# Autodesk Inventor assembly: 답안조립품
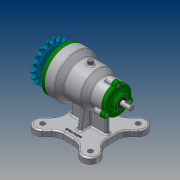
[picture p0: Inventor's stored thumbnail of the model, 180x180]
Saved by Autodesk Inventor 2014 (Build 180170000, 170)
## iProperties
Created: 2017-03
Part Number: 답안조립품
Document SubType Name: Assembly
Designer: Administrator
Author: Administrator
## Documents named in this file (14)
- C:\Users\Administrator\Desktop\470308V1007\답안조립품.iam
- C:\Users\Administrator\Desktop\470308V1007\본체.ipt
- C:\Users\Administrator\Desktop\470308V1007\뒤커버.ipt
- C:\Users\Administrator\Desktop\470308V1007\베어링-6200.ipt
- C:\Users\Administrator\Desktop\470308V1007\베어링-6203.ipt
- C:\Users\Administrator\Desktop\470308V1007\볼트 M4 x 12.ipt
- C:\Users\Administrator\Desktop\470308V1007\볼트 M5 x 10.ipt
- 볼트 M5 x 10.ipt
- C:\Users\Administrator\Desktop\470308V1007\스프로킷.ipt
- C:\Users\Administrator\Desktop\470308V1007\앞커버.ipt
- C:\Users\Administrator\Desktop\470308V1007\오일 실 10 20 7.ipt
- C:\Users\Administrator\Desktop\470308V1007\오일 실 17 30 8.ipt
- C:\Users\Administrator\Desktop\470308V1007\축.ipt
- C:\Users\Administrator\Desktop\470308V1007\키5x5.ipt
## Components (9 placed, 1 different names)
1. ISO 4762 M4 x 12:1 — 각도:4
2. ISO 4762 M4 x 12:3
3. ISO 4762 M4 x 12:4
4. ISO 4762 M4 x 12:2 — 각도:3
5. ISO 4762 M4 x 12:5
6. ISO 4762 M4 x 12:6
7. ISO 4762 M4 x 12:7
8. ISO 4762 M4 x 12:8
9. ISO 4762 M4 x 12:9
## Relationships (2: Angle 2)
- 각도:3 [Angle]: ISO 4762 M4 x 12:2
- 각도:4 [Angle]: ISO 4762 M4 x 12:1
